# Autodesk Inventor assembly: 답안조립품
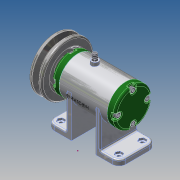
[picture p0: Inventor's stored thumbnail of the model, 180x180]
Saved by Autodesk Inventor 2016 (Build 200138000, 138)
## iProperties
Created: 2017-02
Part Number: 답안조립품
Document SubType Name: Assembly
Designer: Administrator
Author: Administrator
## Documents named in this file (16)
- D:\답안조립품.iam
- D:\본체.ipt
- D:\470208V1007\V벨트풀리.ipt
- D:\470208V1007\너트 M 8.ipt
- D:\470208V1007\니플 M 6 x 0.75.ipt
- D:\470208V1007\뒤커버.ipt
- D:\470208V1007\베어링 15 x 32 x 9.ipt
- D:\470208V1007\볼트 M 6 x 8.ipt
- D:\470208V1007\볼트 M4 x 12.ipt
- D:\470208V1007\스프링와셔 8.ipt
- D:\470208V1007\앞커버.ipt
- D:\470208V1007\오일 실 15 25 7.ipt
- D:\470208V1007\와셔 6x11.5.ipt
- D:\470208V1007\와셔 8x17.ipt
- D:\470208V1007\축.ipt
- D:\470208V1007\키 3 x 3 x 12.ipt
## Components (11 placed, 3 different names)
1. V벨트풀리:1 — 각도:2
2. KS B 2023 6002 - 15 x 32 x 9:1
3. KS B 2023 6002 - 15 x 32 x 9:2
4. ISO 4762 M4 x 12:1
5. ISO 4762 M4 x 12:3
6. ISO 4762 M4 x 12:4
7. ISO 4762 M4 x 12:5
8. ISO 4762 M4 x 12:2
9. ISO 4762 M4 x 12:6
10. ISO 4762 M4 x 12:7
11. ISO 4762 M4 x 12:8
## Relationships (1: Angle 1)
- 각도:2 [Angle]: V벨트풀리:1
